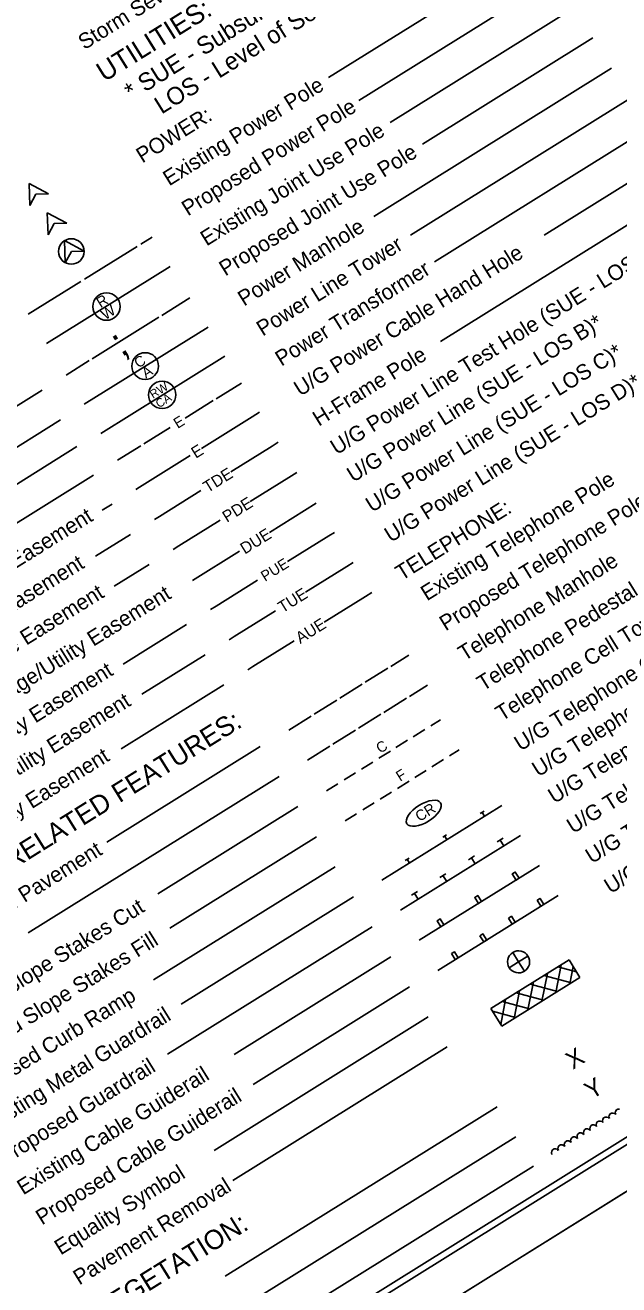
# Model space of a CAD drawing. Extents: x 2046091 to 2048102, y 759061 to 760885.
# Drawn here: x 2047058 to 2047393, y 759460 to 760172 of the extents above; entities that cross this region are included whole.
import ezdxf

# ---------------------------------------------------------------- set-up
doc = ezdxf.new("R2010")
doc.units = 0
for name, color, linetype in [('Prop Easement Permanent Drainage Utility', 7, 'Continuous'), ('Prop WCC CELL', 7, 'Continuous'), ('Sheet Cutting Line CELL', 7, 'Continuous'), ('Sheet Plot Border Inside CELL', 7, 'Continuous'), ('Sheet Plot Border Outside CELL', 7, 'Continuous'), ('Sheet Symbology CELL', 7, 'Continuous')]:
    doc.layers.add(name, color=color, linetype=linetype)

msp = doc.modelspace()

# ---------------------------------------------------------------- linework, layer by layer
at = {"layer": 'Prop Easement Permanent Drainage Utility'}
for p, q in [((2047195.78, 759885.47), (2047222.27, 759901.96)), ((2047152.24, 759858.35), (2047178.81, 759874.89))]:
    msp.add_line(p, q, dxfattribs=at)
at = {"layer": 'Prop WCC CELL'}
msp.add_ellipse((2047283.07, 759726.81), major_axis=(9.52, 5.93), ratio=0.462467, dxfattribs=at)
at = {"layer": 'Sheet Cutting Line CELL'}
msp.add_line((2046672.2, 759061.26), (2048101.59, 759951.6), dxfattribs=at)
at = {"layer": 'Sheet Plot Border Inside CELL'}
msp.add_lwpolyline([(2046671.37, 759087.19), (2048085.9, 759968.28), (2047528.06, 760863.85), (2046113.53, 759982.76)], close=True, dxfattribs=at)
at = {"layer": 'Sheet Plot Border Outside CELL'}
msp.add_lwpolyline([(2046672.2, 759061.26), (2048101.59, 759951.6), (2047520.01, 760885.29), (2046090.62, 759994.95)], close=True, dxfattribs=at)
at = {"layer": 'Sheet Symbology CELL'}
for p, q in [((2047347, 760215.77), (2047229.27, 760142.44)), ((2047357.57, 760198.8), (2047246.45, 760129.58)), ((2047368.14, 760181.82), (2047264.16, 760117.05)), ((2047378.72, 760164.84), (2047282.37, 760104.83)), ((2047389.29, 760147.87), (2047254.76, 760064.07)), ((2047399.87, 760130.89), (2047275.52, 760053.44)), ((2047410.44, 760113.92), (2047289.15, 760038.36)), ((2047421.02, 760096.94), (2047351.14, 760053.41)), ((2047060.29, 760070.25), (2047059.88, 760082.72)), ((2047059.88, 760082.72), (2047070.9, 760076.86)), ((2047431.59, 760079.96), (2047292.47, 759993.31)), ((2047063.69, 760076.61), (2047060.29, 760070.25)), ((2047070.9, 760076.86), (2047063.69, 760076.61)), ((2047070.63, 760053.59), (2047070.22, 760066.06)), ((2047070.22, 760066.06), (2047081.24, 760060.19)), ((2047074.03, 760059.95), (2047070.63, 760053.59)), ((2047081.24, 760060.19), (2047074.03, 760059.95)), ((2047123.06, 760048.44), (2047129.43, 760052.4)), ((2047080.41, 760037.88), (2047080.01, 760050.35)), ((2047080.01, 760050.35), (2047091.02, 760044.49)), ((2047083.81, 760044.24), (2047080.41, 760037.88)), ((2047091.02, 760044.49), (2047083.81, 760044.24)), ((2047091.23, 760028.61), (2047120.94, 760047.11)), ((2047069.74, 759992.19), (2047139.76, 760035.81)), ((2047059.4, 760008.78), (2047089.11, 760027.29)), ((2047135.06, 760008.14), (2047150.87, 760017.98)), ((2047091.12, 759957.87), (2047161.14, 760001.48)), ((2047095.66, 759983.6), (2047133.36, 760007.08)), ((2047080.84, 759974.36), (2047093.97, 759982.54)), ((2047100.5, 759941.43), (2047170.52, 759985.05)), ((2047067.23, 759965.89), (2046998.21, 759922.89)), ((2047165.74, 759961.05), (2047179.95, 759969.9)), ((2047148.13, 759950.08), (2047164.05, 759959.99)), ((2047186.09, 759950.8), (2047190.24, 759953.39)), ((2047077.71, 759949.07), (2047016.9, 759911.19)), ((2047124.79, 759935.54), (2047139.64, 759944.79)), ((2047157.44, 759932.96), (2047186.09, 759950.8)), ((2047087.01, 759933.94), (2047019.65, 759891.98)), ((2047109.93, 759926.28), (2047123.09, 759934.48)), ((2047173.95, 759919.68), (2047197.29, 759934.21)), ((2047197.29, 759934.21), (2047200.81, 759936.41)), ((2047122.43, 759911.15), (2047151.08, 759928.99)), ((2047096.32, 759917.8), (2046994.22, 759854.21)), ((2047184.9, 759902.94), (2047208.24, 759917.48)), ((2047208.24, 759917.48), (2047211.39, 759919.43)), ((2047120.21, 759909.77), (2047122.43, 759911.15)), ((2047133.63, 759894.56), (2047156.97, 759909.1)), ((2047106.93, 759901.49), (2047101.26, 759897.97)), ((2047130.78, 759892.79), (2047133.63, 759894.56)), ((2047144.58, 759877.82), (2047167.93, 759892.36)), ((2047117.18, 759884.32), (2047097.53, 759872.08)), ((2047206.09, 759869), (2047229.43, 759883.54)), ((2047229.43, 759883.54), (2047232.54, 759885.47)), ((2047141.36, 759875.81), (2047144.58, 759877.82)), ((2047127.75, 759867.34), (2047108.1, 759855.1)), ((2047216.25, 759851.76), (2047239.59, 759866.3)), ((2047239.59, 759866.3), (2047243.11, 759868.5)), ((2047165.77, 759843.88), (2047189.11, 759858.42)), ((2047250.16, 759849.33), (2047253.69, 759851.52)), ((2047226.82, 759834.79), (2047250.16, 759849.33)), ((2047162.51, 759841.85), (2047165.77, 759843.88)), ((2047175.93, 759826.65), (2047199.27, 759841.19)), ((2047148.91, 759833.38), (2047113.14, 759811.1)), ((2047173.09, 759824.88), (2047175.93, 759826.65)), ((2047186.5, 759809.67), (2047209.85, 759824.21)), ((2047159.48, 759816.4), (2047123.71, 759794.13)), ((2047264.41, 759809.78), (2047274.6, 759816.13)), ((2047183.66, 759807.9), (2047186.5, 759809.67)), ((2047249.99, 759800.79), (2047262.72, 759808.72)), ((2047170.05, 759799.43), (2047111.95, 759763.23)), ((2047235.56, 759791.8), (2047248.29, 759799.74)), ((2047274.99, 759792.8), (2047285.17, 759799.15)), ((2047221.13, 759782.82), (2047233.86, 759790.75)), ((2047260.56, 759783.82), (2047273.29, 759791.75)), ((2047206.7, 759773.83), (2047219.43, 759781.76)), ((2047246.13, 759774.83), (2047258.86, 759782.76)), ((2047231.7, 759765.84), (2047244.43, 759773.77)), ((2047283.73, 759774.13), (2047277.07, 759769.98)), ((2047292.48, 759779.58), (2047287.04, 759776.19)), ((2047273.93, 759768.02), (2047267.35, 759763.93)), ((2047190.66, 759764.52), (2047103.79, 759710.41)), ((2047217.27, 759756.85), (2047230, 759764.78)), ((2047264.21, 759761.97), (2047257.59, 759757.85)), ((2047303.05, 759762.6), (2047297.62, 759759.22)), ((2047254.24, 759755.76), (2047247.79, 759751.74)), ((2047294.31, 759757.15), (2047287.65, 759753)), ((2047201.24, 759747.54), (2047059.36, 759659.17)), ((2047244.48, 759749.68), (2047238.07, 759745.69)), ((2047274.79, 759744.99), (2047268.17, 759740.87)), ((2047284.5, 759751.05), (2047277.93, 759746.95)), ((2047228.1, 759739.47), (2047234.55, 759743.49)), ((2047264.81, 759738.78), (2047258.36, 759734.76)), ((2047211.81, 759730.57), (2047132.71, 759681.3)), ((2047255.05, 759732.7), (2047248.64, 759728.71)), ((2047259.37, 759688.97), (2047327.27, 759731.26)), ((2047238.67, 759722.5), (2047245.12, 759726.52)), ((2047315.04, 759726.59), (2047317.16, 759727.91)), ((2047317.42, 759725.12), (2047316.1, 759727.25)), ((2047222.39, 759713.59), (2047139.43, 759661.92)), ((2047337.85, 759714.29), (2047269.94, 759671.99)), ((2047293.82, 759713.37), (2047295.94, 759714.69)), ((2047296.2, 759711.91), (2047294.88, 759714.03)), ((2047324.49, 759710.62), (2047327.89, 759712.74)), ((2047328.28, 759708.33), (2047326.19, 759711.68)), ((2047308.37, 759700.58), (2047311.76, 759702.69)), ((2047232.96, 759696.62), (2047130.32, 759632.68)), ((2047272.59, 759700.15), (2047274.72, 759701.47)), ((2047274.98, 759698.69), (2047273.66, 759700.81)), ((2047280.52, 759655.02), (2047348.42, 759697.31)), ((2047312.15, 759698.28), (2047310.06, 759701.63)), ((2047292.24, 759690.53), (2047295.63, 759692.65)), ((2047296.02, 759688.24), (2047293.94, 759691.59)), ((2047276.11, 759680.49), (2047279.51, 759682.6)), ((2047279.9, 759678.19), (2047277.81, 759681.54)), ((2047243.34, 759679.66), (2047145.86, 759618.94)), ((2047291.09, 759638.04), (2047359, 759680.34)), ((2047253.91, 759662.68), (2047138.27, 759590.65)), ((2047264.49, 759645.71), (2047175.96, 759590.56)), ((2047333.36, 759648.15), (2047336.67, 759642.85)), ((2047336.67, 759642.85), (2047341.97, 759646.15)), ((2047320.98, 759616.44), (2047365.2, 759643.98)), ((2047331.36, 759639.54), (2047336.67, 759642.85)), ((2047336.67, 759642.85), (2047339.97, 759637.54)), ((2047357.73, 759625.54), (2047360.83, 759641.26)), ((2047369.41, 759637.24), (2047358.88, 759640.05)), ((2047365.2, 759643.98), (2047371.39, 759634.05)), ((2047365.58, 759630.43), (2047367.53, 759640.25)), ((2047371.39, 759634.05), (2047327.17, 759606.51)), ((2047341.94, 759615.71), (2047345.13, 759631.48)), ((2047349.83, 759620.62), (2047352.98, 759636.37)), ((2047366.55, 759631.04), (2047350.99, 759635.13)), ((2047275.06, 759628.73), (2047186.53, 759573.59)), ((2047334.09, 759610.82), (2047337.24, 759626.56)), ((2047350.76, 759621.21), (2047335.28, 759625.35)), ((2047358.66, 759626.12), (2047343.14, 759630.24)), ((2047321.3, 759615.93), (2047321.45, 759616.73)), ((2047326.56, 759607.48), (2047329.34, 759621.65)), ((2047342.91, 759616.31), (2047327.39, 759620.43)), ((2047285.63, 759611.75), (2047164.57, 759536.35)), ((2047327.17, 759606.51), (2047320.98, 759616.44)), ((2047335.02, 759611.4), (2047321.93, 759614.91)), ((2047296.21, 759594.78), (2047175.15, 759519.37)), ((2047324.49, 759560.98), (2047170.75, 759465.22)), ((2047391.97, 759559.17), (2047392.78, 759559.68)), ((2047392.78, 759559.68), (2047393.72, 759559.67)), ((2047381.15, 759552.43), (2047381.96, 759552.94)), ((2047381.96, 759552.94), (2047382.9, 759552.93)), ((2047382.9, 759552.93), (2047383.71, 759552.67)), ((2047383.71, 759552.67), (2047384.33, 759552.06)), ((2047384.15, 759553.01), (2047384.32, 759553.87)), ((2047384.4, 759552.04), (2047384.15, 759553.01)), ((2047384.32, 759553.87), (2047384.76, 759554.68)), ((2047384.76, 759554.68), (2047385.57, 759555.18)), ((2047385.57, 759555.18), (2047386.51, 759555.18)), ((2047386.51, 759555.18), (2047387.32, 759554.92)), ((2047387.32, 759554.92), (2047387.94, 759554.3)), ((2047387.76, 759555.25), (2047387.93, 759556.12)), ((2047388.01, 759554.29), (2047387.76, 759555.25)), ((2047387.93, 759556.12), (2047388.37, 759556.93)), ((2047388.37, 759556.93), (2047389.17, 759557.43)), ((2047389.17, 759557.43), (2047390.12, 759557.43)), ((2047390.12, 759557.43), (2047390.93, 759557.17)), ((2047390.93, 759557.17), (2047391.55, 759556.55)), ((2047391.37, 759557.5), (2047391.53, 759558.37)), ((2047391.61, 759556.53), (2047391.37, 759557.5)), ((2047391.53, 759558.37), (2047391.97, 759559.17)), ((2047369.89, 759544.89), (2047370.33, 759545.69)), ((2047370.33, 759545.69), (2047371.14, 759546.19)), ((2047371.14, 759546.19), (2047372.08, 759546.19)), ((2047372.08, 759546.19), (2047372.89, 759545.93)), ((2047372.89, 759545.93), (2047373.51, 759545.32)), ((2047373.33, 759546.26), (2047373.5, 759547.13)), ((2047373.58, 759545.3), (2047373.33, 759546.26)), ((2047373.5, 759547.13), (2047373.94, 759547.94)), ((2047373.94, 759547.94), (2047374.74, 759548.44)), ((2047374.74, 759548.44), (2047375.69, 759548.44)), ((2047375.69, 759548.44), (2047376.5, 759548.18)), ((2047376.5, 759548.18), (2047377.12, 759547.56)), ((2047376.94, 759548.51), (2047377.1, 759549.38)), ((2047377.19, 759547.55), (2047376.94, 759548.51)), ((2047377.1, 759549.38), (2047377.54, 759550.19)), ((2047377.54, 759550.19), (2047378.35, 759550.69)), ((2047378.35, 759550.69), (2047379.29, 759550.69)), ((2047379.29, 759550.69), (2047380.1, 759550.43)), ((2047380.1, 759550.43), (2047380.72, 759549.81)), ((2047380.54, 759550.76), (2047380.71, 759551.63)), ((2047380.79, 759549.79), (2047380.54, 759550.76)), ((2047380.71, 759551.63), (2047381.15, 759552.43)), ((2047335.07, 759544), (2047181.33, 759448.24)), ((2047359.07, 759538.15), (2047359.51, 759538.95)), ((2047359.51, 759538.95), (2047360.31, 759539.45)), ((2047360.31, 759539.45), (2047361.26, 759539.45)), ((2047361.26, 759539.45), (2047362.07, 759539.19)), ((2047362.07, 759539.19), (2047362.69, 759538.57)), ((2047362.51, 759539.52), (2047362.67, 759540.39)), ((2047362.76, 759538.56), (2047362.51, 759539.52)), ((2047362.67, 759540.39), (2047363.11, 759541.2)), ((2047363.11, 759541.2), (2047363.92, 759541.7)), ((2047363.92, 759541.7), (2047364.86, 759541.7)), ((2047364.86, 759541.7), (2047365.67, 759541.44)), ((2047365.67, 759541.44), (2047366.29, 759540.82)), ((2047366.12, 759541.77), (2047366.28, 759542.64)), ((2047366.36, 759540.81), (2047366.12, 759541.77)), ((2047366.28, 759542.64), (2047366.72, 759543.44)), ((2047366.72, 759543.44), (2047367.53, 759543.95)), ((2047367.53, 759543.95), (2047368.47, 759543.95)), ((2047368.47, 759543.95), (2047369.28, 759543.68)), ((2047369.28, 759543.68), (2047369.9, 759543.07)), ((2047369.72, 759544.02), (2047369.89, 759544.89)), ((2047369.97, 759543.05), (2047369.72, 759544.02)), ((2047355.29, 759535.03), (2047355.46, 759535.9)), ((2047355.54, 759534.06), (2047355.29, 759535.03)), ((2047355.46, 759535.9), (2047355.9, 759536.7)), ((2047355.9, 759536.7), (2047356.71, 759537.21)), ((2047356.71, 759537.21), (2047357.65, 759537.2)), ((2047357.65, 759537.2), (2047358.46, 759536.94)), ((2047358.46, 759536.94), (2047359.08, 759536.33)), ((2047358.9, 759537.28), (2047359.07, 759538.15)), ((2047359.15, 759536.31), (2047358.9, 759537.28)), ((2047345.02, 759527.51), (2047164.49, 759415.06))]:
    msp.add_line(p, q, dxfattribs=at)
for points in [[(2047518.8, 760855.08), (2046245.59, 760062.02), (2046800.2, 759171.64), (2048073.4, 759964.7)], [(2047335.25, 759689.1), (2047336.94, 759690.16), (2047334.83, 759693.56), (2047333.13, 759692.5)], [(2047314.03, 759675.89), (2047315.72, 759676.94), (2047313.61, 759680.34), (2047311.91, 759679.28)], [(2047347.09, 759677.63), (2047348.79, 759678.69), (2047350.9, 759675.29), (2047349.2, 759674.24)], [(2047292.81, 759662.67), (2047294.5, 759663.73), (2047292.39, 759667.12), (2047290.69, 759666.06)], [(2047330.96, 759667.59), (2047332.66, 759668.64), (2047334.77, 759665.25), (2047333.08, 759664.19)], [(2047314.83, 759657.54), (2047316.53, 759658.6), (2047318.65, 759655.2), (2047316.95, 759654.14)], [(2047298.71, 759647.49), (2047300.4, 759648.55), (2047302.52, 759645.16), (2047300.82, 759644.1)]]:
    msp.add_lwpolyline(points, close=True, dxfattribs=at)
for centre, radius in [((2047083.81, 760044.24), 7.2), ((2047103.67, 760013.09), 7.75), ((2047125.56, 759979.45), 7.58), ((2047135.21, 759963.23), 7.72)]:
    msp.add_circle(centre, radius, dxfattribs=at)
for start, end in [(121.91242, 211.91696), (31.91242, 121.91696), (301.91242, 31.91696), (211.91242, 301.91696)]:
    msp.add_arc((2047336.67, 759642.85), 6.25, start, end, dxfattribs=at)

# ---------------------------------------------------------------- texts
at = {"layer": 'Prop Easement Permanent Drainage Utility'}
msp.add_text('DUE', height=6.55, rotation=31.91803, dxfattribs=at).set_placement((2047181.9, 759872.93))
at = {"layer": 'Prop WCC CELL'}
msp.add_text('CR', height=6, rotation=31.91803, dxfattribs=at).set_placement((2047280.63, 759721.81))
at = {"layer": 'Sheet Symbology CELL'}
for s, height, p in [('LOS - Level of Service - A,B,C or D (Accuracy) ', 9.9, (2047134.8, 760121.51)), ('* SUE - Subsurface Utility Engineering', 9.9, (2047117.86, 760129.3)), ('Storm Sewer', 8.75, (2047091.18, 760157.9)), ('UTILITIES:', 11, (2047102.46, 760139.76)), ('Existing Power Pole', 8.75, (2047139.11, 760080.94)), ('Proposed Power Pole', 8.75, (2047149.69, 760063.97)), ('POWER:', 8.75, (2047123.94, 760093.88)), ('Existing Joint Use Pole', 8.75, (2047160.26, 760047)), ('Proposed Joint Use Pole', 8.75, (2047170.85, 760030.02)), ('Power Manhole', 8.75, (2047181.42, 760013.04)), ('Power Line Tower', 8.75, (2047191.99, 759996.08)), ('U/G Power Line Test Hole (SUE - LOS A)*', 8.75, (2047233.76, 759929.04)), ('U/G Power Cable Hand Hole', 8.75, (2047213.15, 759962.12)), ('Power Transformer', 8.75, (2047202.55, 759979.1)), ('R', 6.08, (2047100.36, 760012.09)), ('W', 6.08, (2047102.97, 760005.29)), ('U/G Power Line (SUE - LOS B)*', 8.75, (2047243.13, 759913.47)), (';', 16.5, (2047112.16, 759984.22)), ('H-Frame Pole', 8.75, (2047223.73, 759945.15)), ('U/G Power Line (SUE - LOS C)*', 8.75, (2047253.74, 759896.5)), ('C', 5.94, (2047121.67, 759978.07)), ('A', 5.94, (2047125.95, 759972.33)), ('U/G Power Line (SUE - LOS D)*', 8.75, (2047264.34, 759879.53)), ('RW', 4.838, (2047129.99, 759960.88)), ('CA', 4.838, (2047133.37, 759955.58)), ('E', 6, (2047143.95, 759943.94)), ('E', 6.55, (2047154.18, 759927.04)), ('TDE', 6.55, (2047160.92, 759907.67)), ('Existing Telephone Pole', 8.75, (2047284.84, 759846.51)), ('PDE', 6.55, (2047171.79, 759890.88)), ('TELEPHONE:', 8.75, (2047270.56, 759857.99)), ('Proposed Telephone Pole', 8.75, (2047295.42, 759829.54)), ('Proposed Temporary Construction Easement', 8.75, (2046897.51, 759768.38)), ('Telephone Manhole', 8.75, (2047305.99, 759812.56)), ('Proposed Temporary Drainage Easement', 8.75, (2046908.08, 759751.41)), ('PUE', 6, (2047193.33, 759857.52)), ('U/G Telephone Test Hole (SUE - LOS A)*', 8.75, (2047347.77, 759747.07)), ('Proposed Permanent Drainage Easement', 8.75, (2046918.66, 759734.43)), ('Proposed Permanent Drainage/Utility Easement', 8.75, (2046929.54, 759716.96)), ('TUE', 6.55, (2047203.21, 759839.75)), ('Telephone Pedestal', 8.75, (2047316.56, 759795.59)), ('U/G Telephone Cable Hand Hole', 8.75, (2047337.72, 759761.64)), ('Telephone Cell Tower', 8.75, (2047327.15, 759778.62)), ('AUE', 6.55, (2047213.22, 759822.43)), ('U/G Telephone Cable (SUE - LOS B)*', 8.75, (2047356.85, 759731.97)), ('U/G Telephone Cable (SUE - LOS C)*', 8.75, (2047367.42, 759714.99)), ('Proposed Permanent Utility Easement', 8.75, (2046939.81, 759700.47)), ('U/G Telephone Cable (SUE - LOS D)*', 8.75, (2047378, 759698.02)), ('U/G Telephone Conduit (SUE - LOS B)*', 8.75, (2047388.57, 759681.04)), ('Proposed Temporary Utility Easement', 8.75, (2046950.38, 759683.5)), ('ROADS AND RELATED FEATURES:', 11, (2046972.27, 759645.97)), ('C', 5.93, (2047258.41, 759760.4)), ('Proposed Aerial Utility Easement', 8.75, (2046960.96, 759666.52)), ('F', 5.93, (2047269.68, 759744.59)), ('Existing Edge of Pavement', 8.75, (2046982.78, 759629.67)), ('Proposed Slope Stakes Cut', 8.75, (2047003.93, 759595.72)), ('Proposed Slope Stakes Fill', 8.75, (2047014.5, 759578.74)), ('Proposed Curb Ramp', 8.75, (2047025.07, 759561.77)), ('Existing Metal Guardrail', 8.75, (2047035.45, 759544.81)), ('Proposed Guardrail', 8.75, (2047046.03, 759527.85)), ('X', 10, (2047367.36, 759581.79)), ('Existing Cable Guiderail', 8.75, (2047056.6, 759510.87)), ('Y', 10, (2047377.94, 759564.81)), ('Proposed Cable Guiderail', 8.75, (2047067.18, 759493.9)), ('Equality Symbol', 8.75, (2047077.75, 759476.92)), ('Pavement Removal', 8.75, (2047088.33, 759459.95)), ('VEGETATION:', 11, (2047100.82, 759439.86))]:
    msp.add_text(s, height=height, rotation=31.91803, dxfattribs=at).set_placement(p)

doc.saveas('drawing.dxf')
